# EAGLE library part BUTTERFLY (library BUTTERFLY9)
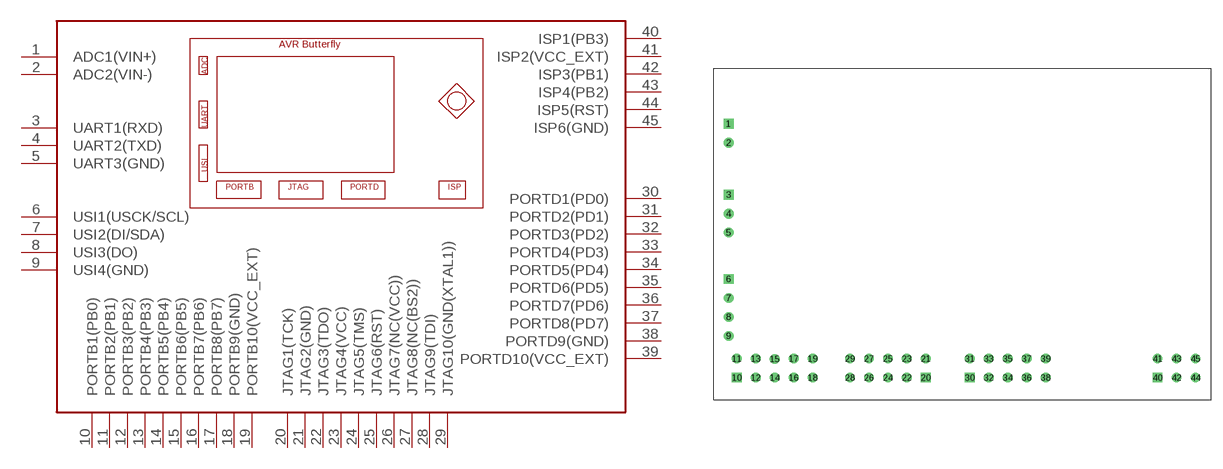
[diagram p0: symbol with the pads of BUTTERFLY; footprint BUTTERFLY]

Designator prefix -

## BUTTERFLY  [BUTTERFLY]
1  ADC1(VIN+)
2  ADC2(VIN-)
3  UART1(RXD)
4  UART2(TXD)
5  UART3(GND)
6  USI1(USCK/SCL)
7  USI2(DI/SDA)
8  USI3(DO)
9  USI4(GND)
10  PORTB1(PB0)
11  PORTB2(PB1)
12  PORTB3(PB2)
13  PORTB4(PB3)
14  PORTB5(PB4)
15  PORTB6(PB5)
16  PORTB7(PB6)
17  PORTB8(PB7)
18  PORTB9(GND)
19  PORTB10(VCC_EXT)
20  JTAG1(TCK)
21  JTAG2(GND)
22  JTAG3(TDO)
23  JTAG4(VCC)
24  JTAG5(TMS)
25  JTAG6(RST)
26  JTAG7(NC(VCC))
27  JTAG8(NC(BS2))
28  JTAG9(TDI)
29  JTAG10(GND(XTAL1))
30  PORTD1(PD0)
31  PORTD2(PD1)
32  PORTD3(PD2)
33  PORTD4(PD3)
34  PORTD5(PD4)
35  PORTD6(PD5)
36  PORTD7(PD6)
37  PORTD8(PD7)
38  PORTD9(GND)
39  PORTD10(VCC_EXT)
40  ISP1(PB3)
41  ISP2(VCC_EXT)
42  ISP3(PB1)
43  ISP4(PB2)
44  ISP5(RST)
45  ISP6(GND)

## Footprint BUTTERFLY (pad centres in mm)
drill 0.8 square: 1 2,37; 3 2,27.5; 6 2,16.2; 10 3.1,3; 20 28.42,3; 30 34.32,3; 40 59.48,3
drill 0.8 round: 2 2,34.46; 4 2,24.96; 5 2,22.42; 7 2,13.66; 8 2,11.12; 9 2,8.58; 11 3.1,5.54; 12 5.64,3; 13 5.64,5.54; 14 8.18,3; 15 8.18,5.5; 16 10.72,3; 17 10.72,5.54; 18 13.26,3; 19 13.26,5.54; 21 28.42,5.54; 22 25.88,3; 23 25.88,5.54; 24 23.34,3; 25 23.34,5.54; 26 20.8,3; 27 20.8,5.54; 28 18.26,3; 29 18.26,5.54; 31 34.32,5.54; 32 36.86,3; 33 36.86,5.54; 34 39.4,3; 35 39.4,5.54; 36 41.94,3; 37 41.94,5.54; 38 44.48,3; 39 44.48,5.54; 41 59.48,5.54; 42 62.02,3; 43 62.02,5.54; 44 64.56,3; 45 64.56,5.54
